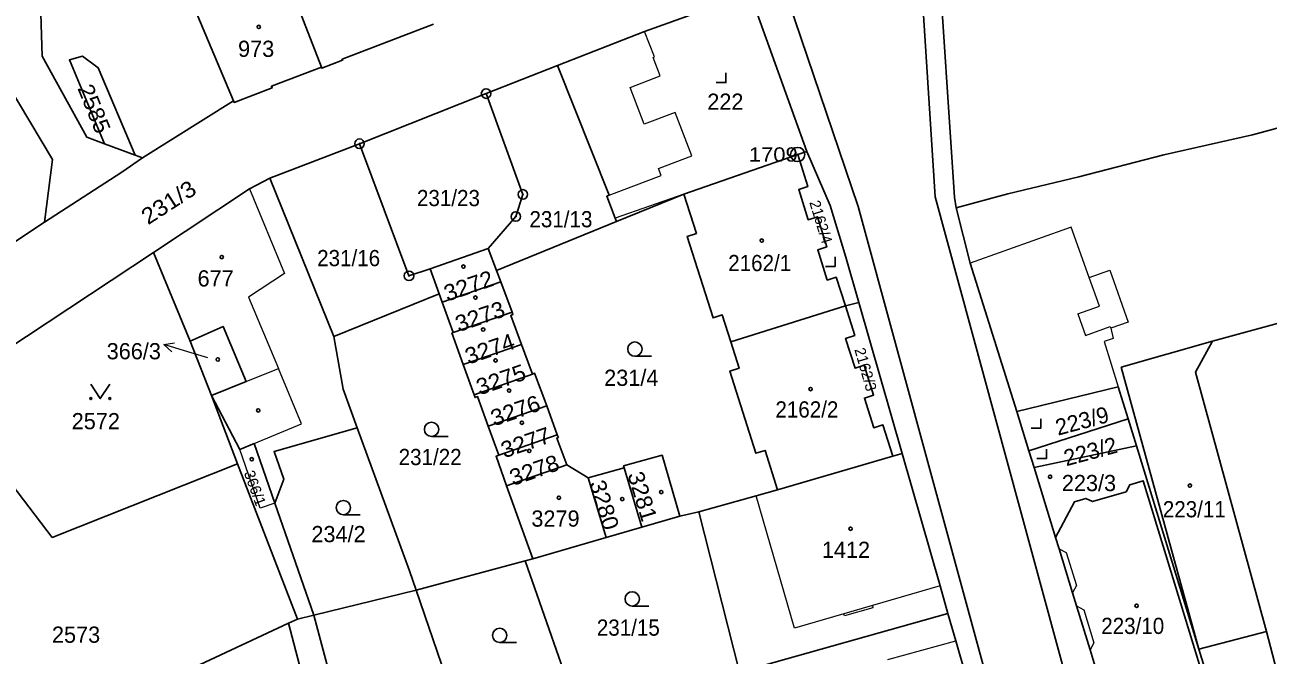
# Model space of a CAD drawing. Extents: x -679733 to -673243, y -1075091 to -1066557.
# Drawn here: x -676227.8 to -676097.4, y -1071687 to -1071620.8 of the extents above; entities that cross this region are included whole.
import ezdxf
from ezdxf.enums import TextEntityAlignment as Align

# ---------------------------------------------------------------- set-up
doc = ezdxf.new("R2010")
doc.units = 0
doc.header["$LTSCALE"] = 0.68
for name, color, linetype, lineweight in [('1', 7, 'Continuous', 25), ('3', 7, 'Continuous', 25), ('4', 7, 'Continuous', 13), ('5', 7, 'Continuous', 25), ('7', 7, 'Continuous', 13), ('8', 7, 'Continuous', 25)]:
    doc.layers.add(name, color=color, linetype=linetype, lineweight=lineweight)
doc.layers.add('2', color=7, linetype='Continuous')

msp = doc.modelspace()

# ---------------------------------------------------------------- linework, layer by layer
at = {"layer": '1'}
for p, q in [((-676145.76, -1071634.12), (-676151.72, -1071617.55)), ((-676216.21, -1071634.52), (-676219.43, -1071633.33)), ((-676158.64, -1071638.61), (-676146.7, -1071634.45)), ((-676165.71, -1071641.49), (-676178.31, -1071646.61)), ((-676195.37, -1071653.55), (-676184.32, -1071649.06)), ((-676184, -1071649.93), (-676182.84, -1071653.13)), ((-676153.73, -1071654.12), (-676141.7, -1071650.33)), ((-676210.42, -1071654.02), (-676208.21, -1071659.74)), ((-676174.53, -1071657.5), (-676175.68, -1071654.37)), ((-676112.77, -1071656.77), (-676103.2, -1071654.04)), ((-676171.92, -1071663.86), (-676173.03, -1071660.83)), ((-676112.02, -1071662.17), (-676122.44, -1071665.53)), ((-676121.9, -1071667.28), (-676111.15, -1071665.03)), ((-676136.74, -1071666.1), (-676148.81, -1071669.62)), ((-676168.68, -1071668.36), (-676170.92, -1071667.01)), ((-676177.24, -1071669.21), (-676174.48, -1071676.86)), ((-676197.47, -1071682.78), (-676201.55, -1071671.02)), ((-676163.04, -1071673.55), (-676159.05, -1071672.4)), ((-676159.05, -1071672.4), (-676157.09, -1071671.95)), ((-676175.28, -1071677.08), (-676186.72, -1071680.18)), ((-676186.72, -1071680.18), (-676197.47, -1071682.78)), ((-676152.82, -1071688.75), (-676130.95, -1071682.6))]:
    msp.add_line(p, q, dxfattribs=at)
for points in [[(-676099.38, -1071590.43), (-676125.1, -1071603.36), (-676134.03, -1071611.63), (-676132.28, -1071638.9), (-676113.31, -1071708.7), (-676111.17, -1071722.51), (-676112.16, -1071739.84), (-676114.63, -1071749.43), (-676121.41, -1071764.03), (-676135.15, -1071783.33), (-676142.46, -1071792.76), (-676166.36, -1071822.04), (-676175.39, -1071833.12), (-676182.45, -1071844.4), (-676187.2, -1071855.01), (-676191.45, -1071871.27), (-676192.51, -1071884.43), (-676191.2, -1071899.37), (-676183.88, -1071917.06), (-676171.89, -1071936.65), (-676157.14, -1071950.29), (-676143.77, -1071959.8), (-676108.24, -1071982.64), (-676103.47, -1071979.82)], [(-676130.08, -1071640.05), (-676130.27, -1071638.92), (-676132.05, -1071612.1), (-676123.87, -1071605), (-676098.3, -1071593.66), (-676099.38, -1071590.43)], [(-676254.27, -1071592.33), (-676250.44, -1071598.38), (-676250.16, -1071598.2), (-676242.88, -1071609.41), (-676233.68, -1071603.54), (-676226.09, -1071619.69), (-676225.97, -1071624.14), (-676221.28, -1071632.65), (-676219.43, -1071633.33)], [(-676196.67, -1071625.28), (-676200.44, -1071615.54), (-676201.03, -1071614.01), (-676202.2, -1071610.84), (-676203.22, -1071608.14), (-676204.4, -1071605.31)], [(-676205.88, -1071628.82), (-676209.9, -1071619.28), (-676212.5, -1071613.48), (-676214.24, -1071609.44)], [(-676152.11, -1071615.93), (-676148.36, -1071616.28), (-676140.37, -1071639.9), (-676120.56, -1071712.56)], [(-676151.72, -1071617.55), (-676162.77, -1071621.53), (-676171.89, -1071625.11)], [(-676196.67, -1071625.28), (-676196.63, -1071625.4), (-676194.45, -1071624.56), (-676194.49, -1071624.45), (-676184.92, -1071620.78)], [(-676219.43, -1071633.33), (-676223.1, -1071624.53), (-676221.72, -1071624.15), (-676220.07, -1071625.35), (-676216.21, -1071634.52), (-676215.43, -1071634.8), (-676205.88, -1071628.82)], [(-676205.88, -1071628.82), (-676205.82, -1071628.99), (-676201.84, -1071627.46), (-676201.9, -1071627.29), (-676196.67, -1071625.28)], [(-676202.07, -1071636.95), (-676192.67, -1071633.32), (-676179.39, -1071628.06), (-676171.89, -1071625.11)], [(-676171.89, -1071625.11), (-676166.49, -1071638.73), (-676166.73, -1071638.83), (-676165.85, -1071641.12), (-676165.71, -1071641.49), (-676158.64, -1071638.61)], [(-676084.03, -1071625.87), (-676089.49, -1071628.58), (-676093.25, -1071630.57), (-676095.5, -1071631.44), (-676098.98, -1071632.38), (-676108.29, -1071634.5), (-676117.2, -1071636.81), (-676124.66, -1071638.59), (-676130.08, -1071640.05)], [(-676246.86, -1071632.02), (-676229.61, -1071626.99), (-676224.86, -1071634.98), (-676225.72, -1071641.56)], [(-676179.39, -1071628.06), (-676175.53, -1071638.64), (-676176.27, -1071640.96), (-676179.16, -1071644.33)], [(-676185.27, -1071646.43), (-676187.48, -1071647.18), (-676192.67, -1071633.32)], [(-676225.72, -1071641.56), (-676217.6, -1071636.32), (-676215.43, -1071634.8)], [(-676140.29, -1071649.98), (-676141.65, -1071645.22), (-676143.3, -1071639.79), (-676145.76, -1071634.12), (-676146.7, -1071634.45)], [(-676146.7, -1071634.45), (-676145.64, -1071637.82), (-676146.59, -1071638.12), (-676145.6, -1071641.29), (-676144.64, -1071640.99), (-676143.65, -1071644.15), (-676144.6, -1071644.45), (-676143.6, -1071647.63), (-676142.65, -1071647.33), (-676141.7, -1071650.33)], [(-676202.07, -1071636.95), (-676204.21, -1071638.05), (-676214.28, -1071644.72), (-676210.42, -1071654.02)], [(-676192.9, -1071663.12), (-676194.37, -1071659.08), (-676195.37, -1071653.55), (-676202.07, -1071636.95)], [(-676158.64, -1071638.61), (-676157.33, -1071642.74), (-676158.28, -1071643.05), (-676155.58, -1071651.59), (-676154.62, -1071651.29), (-676153.73, -1071654.12)], [(-676241.62, -1071640.83), (-676239.22, -1071639.46), (-676235.09, -1071647.75), (-676225.72, -1071641.56)], [(-676130.08, -1071640.05), (-676128.61, -1071645.86), (-676123.73, -1071661.42)], [(-676244.34, -1071664.59), (-676236.52, -1071659.42), (-676214.28, -1071644.72)], [(-676182.84, -1071653.13), (-676176.67, -1071651.01), (-676177.86, -1071647.82)], [(-676103.2, -1071654.04), (-676086.03, -1071649.36), (-676082.9, -1071651.16), (-676076.65, -1071673.87), (-676071.5, -1071672.48), (-676068, -1071685.48), (-676073.36, -1071686.93), (-676072.45, -1071689.95), (-676094.51, -1071696.03), (-676097.54, -1071684.49)], [(-676136.74, -1071666.1), (-676135.76, -1071665.81), (-676140.29, -1071649.98), (-676141.7, -1071650.33)], [(-676141.7, -1071650.33), (-676140.72, -1071653.44), (-676141.68, -1071653.74), (-676140.69, -1071656.87), (-676139.74, -1071656.57), (-676138.75, -1071659.7), (-676139.71, -1071660), (-676138.72, -1071663.13), (-676137.77, -1071662.83), (-676136.74, -1071666.1)], [(-676175.68, -1071654.37), (-676176.81, -1071651.34), (-676176.58, -1071651.24), (-676176.67, -1071651.01)], [(-676208.21, -1071659.74), (-676204.56, -1071658.27), (-676206.98, -1071652.49), (-676210.42, -1071654.02)], [(-676182.84, -1071653.13), (-676182.98, -1071653.18), (-676181.78, -1071656.49), (-676175.68, -1071654.37)], [(-676153.73, -1071654.12), (-676152.85, -1071656.88), (-676153.81, -1071657.18), (-676151.08, -1071665.8), (-676150.12, -1071665.5), (-676148.81, -1071669.62)], [(-676103.2, -1071654.04), (-676104.96, -1071657.29), (-676097.54, -1071684.49)], [(-676181.78, -1071656.49), (-676180.65, -1071659.66), (-676174.53, -1071657.5)], [(-676173.03, -1071660.83), (-676174.3, -1071657.41), (-676174.53, -1071657.5)], [(-676097.54, -1071684.49), (-676104.63, -1071686.35), (-676112.77, -1071656.77)], [(-676236.52, -1071659.42), (-676224.9, -1071674.63), (-676205.45, -1071666.89)], [(-676201.55, -1071671.02), (-676203.72, -1071664.79), (-676205.23, -1071665.42), (-676208.21, -1071659.74), (-676205.45, -1071666.89), (-676199.16, -1071683.19)], [(-676180.65, -1071659.66), (-676180.54, -1071659.95), (-676180.28, -1071659.86), (-676179.17, -1071662.97), (-676173.03, -1071660.83)], [(-676123.73, -1071661.42), (-676113.07, -1071658.83), (-676112.02, -1071662.17), (-676111.15, -1071665.03)], [(-676112.37, -1071698.39), (-676114.06, -1071692.92), (-676115.61, -1071687.82), (-676116.03, -1071686.43), (-676117.44, -1071681.82), (-676117.87, -1071680.43), (-676119.29, -1071675.81), (-676119.65, -1071674.63), (-676121.9, -1071667.28), (-676122.44, -1071665.53), (-676123.73, -1071661.42)], [(-676201.55, -1071671.02), (-676200.62, -1071668.53), (-676201.63, -1071665.6), (-676192.9, -1071663.12)], [(-676192.9, -1071663.12), (-676187.41, -1071678.15), (-676186.72, -1071680.18)], [(-676179.17, -1071662.97), (-676178.07, -1071666.01), (-676171.92, -1071663.86)], [(-676170.92, -1071667.01), (-676171.97, -1071664.2), (-676171.81, -1071664.14), (-676171.92, -1071663.86)], [(-676111.15, -1071665.03), (-676104.63, -1071686.35), (-676101.17, -1071697.56), (-676111.57, -1071700.93)], [(-676178.07, -1071666.01), (-676178.35, -1071666.11), (-676177.24, -1071669.21), (-676170.92, -1071667.01)], [(-676159.05, -1071672.4), (-676160.92, -1071666), (-676164.96, -1071667.12), (-676164.91, -1071667.31)], [(-676130.95, -1071682.6), (-676131.76, -1071679.71), (-676135.76, -1071665.81)], [(-676166.79, -1071674.64), (-676163.04, -1071673.55), (-676164.91, -1071667.31), (-676168.68, -1071668.36)], [(-676174.48, -1071676.86), (-676166.79, -1071674.64), (-676168.68, -1071668.36)], [(-676119.65, -1071674.63), (-676117.65, -1071670.88), (-676116.48, -1071670.53), (-676115.77, -1071670.87), (-676112.25, -1071669.86), (-676111.85, -1071669.11), (-676110.46, -1071668.68), (-676102.32, -1071695.32), (-676112.37, -1071698.39)], [(-676148.81, -1071669.62), (-676151.07, -1071670.28), (-676157.09, -1071671.95), (-676152.82, -1071688.75), (-676148.14, -1071704.96), (-676145.33, -1071704.18)], [(-676174.48, -1071676.86), (-676175.28, -1071677.08), (-676169.53, -1071693.6)], [(-676186.72, -1071680.18), (-676184.08, -1071687.93), (-676181.15, -1071696.97)], [(-676197.47, -1071682.78), (-676199.16, -1071683.19), (-676200.12, -1071683.64)], [(-676192.41, -1071730.27), (-676191.7, -1071728.73), (-676189.75, -1071721.53), (-676189.03, -1071719.16), (-676188.8, -1071717.45), (-676189.32, -1071714.46), (-676189.96, -1071710.82), (-676197.47, -1071682.78)], [(-676126.28, -1071698.88), (-676130.13, -1071685.49), (-676130.95, -1071682.6)], [(-676200.12, -1071683.64), (-676207.81, -1071687.24), (-676210.49, -1071688.47)], [(-676194.94, -1071729.17), (-676194.02, -1071726.7), (-676191.74, -1071718.18), (-676192.25, -1071715.23), (-676193.04, -1071710.6), (-676200.12, -1071683.64)]]:
    msp.add_lwpolyline(points, dxfattribs=at)
msp.add_lwpolyline([(-676177.86, -1071647.82), (-676178.31, -1071646.61), (-676179.16, -1071644.33), (-676185.27, -1071646.43), (-676184.32, -1071649.06), (-676184, -1071649.93)], close=True, dxfattribs=at)
at = {"layer": '3'}
for p, q in [((-676163.783, -1071655.62), (-676162.033, -1071655.62)), ((-676185.113, -1071664.04), (-676183.363, -1071664.04)), ((-676194.363, -1071672.25), (-676192.613, -1071672.25)), ((-676164.063, -1071681.83), (-676162.313, -1071681.83)), ((-676177.963, -1071685.66), (-676176.213, -1071685.66))]:
    msp.add_line(p, q, dxfattribs=at)
for points in [[(-676155.241, -1071626.9), (-676154.24, -1071626.9), (-676154.24, -1071625.9)], [(-676143.781, -1071646.2), (-676142.78, -1071646.2), (-676142.78, -1071645.2)], [(-676220.86, -1071658.559), (-676219.86, -1071660.06), (-676218.86, -1071658.559)], [(-676122.211, -1071663.18), (-676121.21, -1071663.18), (-676121.21, -1071662.18)], [(-676121.621, -1071666.36), (-676120.62, -1071666.36), (-676120.62, -1071665.36)]]:
    msp.add_lwpolyline(points, dxfattribs=at)
for centre, radius in [((-676163.7829, -1071654.8698), 0.75), ((-676220.86, -1071660.0595), 0.1), ((-676218.86, -1071660.0595), 0.1), ((-676185.1129, -1071663.2898), 0.75), ((-676194.3629, -1071671.4998), 0.75), ((-676164.0629, -1071681.0798), 0.75), ((-676177.9629, -1071684.9098), 0.75)]:
    msp.add_circle(centre, radius, dxfattribs=at)
at = {"layer": '4'}
for p, q in [((-676161.74, -1071624.21), (-676162.77, -1071621.53)), ((-676161.86, -1071624.26), (-676161.74, -1071624.21)), ((-676161.12, -1071626.2), (-676161.86, -1071624.26)), ((-676164.28, -1071627.41), (-676161.12, -1071626.2)), ((-676162.8, -1071631.28), (-676164.28, -1071627.41)), ((-676159.55, -1071630.04), (-676162.8, -1071631.28)), ((-676157.81, -1071634.59), (-676159.55, -1071630.04)), ((-676161.3, -1071635.93), (-676157.81, -1071634.59)), ((-676161.02, -1071636.64), (-676161.3, -1071635.93)), ((-676166.49, -1071638.73), (-676161.02, -1071636.64)), ((-676204.21, -1071638.05), (-676200.54, -1071646.93)), ((-676158.64, -1071638.61), (-676165.85, -1071641.12)), ((-676118.02, -1071642.07), (-676128.61, -1071645.86)), ((-676116.13, -1071647.34), (-676118.02, -1071642.07)), ((-676200.54, -1071646.93), (-676204.31, -1071649.42)), ((-676116.13, -1071647.34), (-676113.96, -1071646.58)), ((-676113.96, -1071646.58), (-676112.05, -1071652.06)), ((-676115.05, -1071650.36), (-676116.13, -1071647.34)), ((-676204.31, -1071649.42), (-676201.16, -1071656.91)), ((-676117.31, -1071651.17), (-676115.05, -1071650.36)), ((-676117.31, -1071651.17), (-676116.5, -1071653.43)), ((-676112.05, -1071652.06), (-676113.86, -1071652.69)), ((-676116.5, -1071653.43), (-676113.91, -1071652.5)), ((-676113.91, -1071652.5), (-676113.86, -1071652.69)), ((-676113.86, -1071652.69), (-676113.6, -1071653.76)), ((-676113.6, -1071653.76), (-676114.54, -1071654.08)), ((-676114.54, -1071654.08), (-676113.07, -1071658.83)), ((-676204.56, -1071658.27), (-676201.16, -1071656.91)), ((-676198.74, -1071662.7), (-676201.16, -1071656.91)), ((-676203.72, -1071664.79), (-676198.74, -1071662.7)), ((-676203.1, -1071671.56), (-676205.23, -1071665.42)), ((-676147.05, -1071684.14), (-676151.07, -1071670.28)), ((-676201.55, -1071671.02), (-676203.1, -1071671.56)), ((-676119.29, -1071675.81), (-676118.54, -1071676.2)), ((-676118.54, -1071676.2), (-676117.47, -1071679.67)), ((-676131.76, -1071679.71), (-676138.87, -1071681.77)), ((-676117.47, -1071679.67), (-676117.87, -1071680.43)), ((-676138.87, -1071681.77), (-676141.85, -1071682.64)), ((-676138.81, -1071682), (-676141.78, -1071682.86)), ((-676138.87, -1071681.77), (-676138.81, -1071682)), ((-676117.44, -1071681.82), (-676116.69, -1071682.22)), ((-676116.69, -1071682.22), (-676115.64, -1071685.69)), ((-676141.85, -1071682.64), (-676147.05, -1071684.14)), ((-676141.78, -1071682.86), (-676141.85, -1071682.64)), ((-676137.25, -1071687.44), (-676130.13, -1071685.49)), ((-676115.64, -1071685.69), (-676116.03, -1071686.43))]:
    msp.add_line(p, q, dxfattribs=at)
at = {"layer": '5'}
for centre in [(-676203.2368, -1071621.0592), (-676150.4768, -1071643.4792), (-676207.1168, -1071645.2192), (-676181.7668, -1071646.2092), (-676180.5068, -1071649.4692), (-676179.6968, -1071652.8292), (-676207.5368, -1071655.9592), (-676178.3968, -1071656.0492), (-676176.9768, -1071659.2192), (-676145.3568, -1071659.0592), (-676203.2868, -1071661.2992), (-676175.6268, -1071662.5992), (-676203.9768, -1071666.4192), (-676174.8668, -1071665.5592), (-676120.2268, -1071668.2592), (-676105.5568, -1071669.1892), (-676171.7568, -1071670.4692), (-676165.1068, -1071670.5992), (-676161.0168, -1071669.8692), (-676141.1568, -1071673.7192), (-676111.1468, -1071681.7892)]:
    msp.add_circle(centre, 0.175, dxfattribs=at)
at = {"layer": '7'}
msp.add_line((-676213.18, -1071654.393), (-676212.369, -1071655.164), dxfattribs=at)
msp.add_lwpolyline([(-676208.57, -1071655.8), (-676210.31, -1071655.27), (-676213.18, -1071654.393), (-676212.076, -1071654.207)], dxfattribs=at)
at = {"layer": '8'}
for centre, radius in [((-676179.39, -1071628.0599), 0.5), ((-676179.39, -1071628.0599), 0.0303), ((-676192.67, -1071633.3199), 0.5), ((-676192.67, -1071633.3199), 0.0303), ((-676146.7, -1071634.4498), 0.75), ((-676146.7, -1071634.4498), 0.03), ((-676175.53, -1071638.6399), 0.5), ((-676175.53, -1071638.6399), 0.0303), ((-676176.27, -1071640.9599), 0.5), ((-676176.27, -1071640.9599), 0.0303), ((-676187.48, -1071647.1799), 0.5), ((-676187.48, -1071647.1799), 0.0303)]:
    msp.add_circle(centre, radius, dxfattribs=at)

# ---------------------------------------------------------------- texts
at = {"layer": '2'}
for s, p in [('973', (-676203.509, -1071624.21)), ('222', (-676154.289, -1071629.759)), ('677', (-676207.759, -1071648.3)), ('231/4', (-676164.16, -1071658.729)), ('2572', (-676220.33, -1071663.279)), ('223/3', (-676116.15, -1071669.769)), ('3279', (-676172.11, -1071673.499)), ('234/2', (-676194.87, -1071675.13)), ('1412', (-676141.64, -1071676.779)), ('2573', (-676222.4, -1071685.68))]:
    msp.add_text(s, height=1.7, dxfattribs=at).set_placement(p, align=Align.CENTER)
for s, rotation, width, p in [('2585', 292, 1.05, (-676221.282, -1071629.9601)), ('231/3', 33, 1.1, (-676212.2284, -1071640.1821)), ('3272', 19, 1.05, (-676180.9482, -1071649.0293)), ('3273', 19, 1.05, (-676179.7582, -1071652.2393)), ('3274', 19, 1.05, (-676178.7282, -1071655.6393)), ('3275', 19, 1.05, (-676177.5582, -1071658.8693)), ('3276', 19, 1.05, (-676176.0382, -1071662.1193)), ('3277', 19, 1.05, (-676174.9682, -1071665.4693)), ('3278', 19, 1.05, (-676174.0582, -1071668.3693)), ('3281', 287, 1.05, (-676163.8013, -1071670.5635)), ('3280', 287, 1.05, (-676167.8013, -1071671.4635))]:
    msp.add_text(s, height=1.7, rotation=rotation, dxfattribs=dict(at, width=width)).set_placement(p, align=Align.CENTER)
at = {"layer": '2', "width": 0.95}
for s, p in [('231/23', (-676183.339, -1071639.87)), ('231/13', (-676171.539, -1071642.09)), ('231/16', (-676193.809, -1071646.17)), ('2162/1', (-676150.689, -1071646.69)), ('2162/2', (-676145.739, -1071662.05)), ('231/22', (-676185.259, -1071667.04)), ('223/11', (-676105.099, -1071672.519)), ('231/15', (-676164.469, -1071684.94)), ('223/10', (-676111.559, -1071684.759))]:
    msp.add_text(s, height=1.7, dxfattribs=at).set_placement(p, align=Align.CENTER)
at = {"layer": '2'}
for s, rotation, p in [('2162/4', 287, (-676145.495, -1071639.466)), ('2162/3', 286, (-676140.767, -1071654.907)), ('366/1', 290, (-676204.815, -1071667.854))]:
    msp.add_text(s, height=1.14, rotation=rotation, dxfattribs=at).set_placement(p)
msp.add_text('366/3', height=1.7, dxfattribs=at).set_placement((-676213.499, -1071655.94), align=Align.RIGHT)
for s, p in [('223/9', (-676116.6525, -1071663.2209)), ('223/2', (-676115.7825, -1071666.4309))]:
    msp.add_text(s, height=1.7, rotation=15, dxfattribs=at).set_placement(p, align=Align.CENTER)
at = {"layer": '8', "width": 1.15}
msp.add_text('1709', height=1.5, dxfattribs=at).set_placement((-676146.699, -1071635.2), align=Align.RIGHT)

doc.saveas('drawing.dxf')
